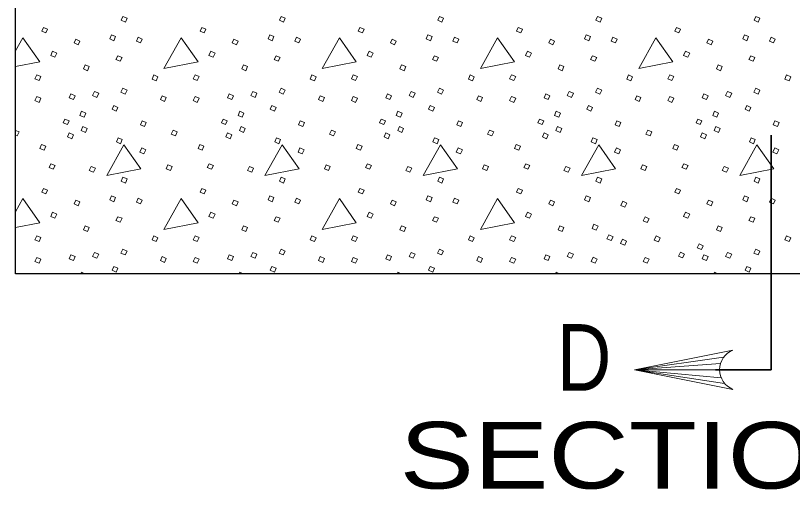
# Model space of a CAD drawing. Extents: x 1036.7 to 1070.7, y 883.9 to 905.9.
# Drawn here: x 1051.372 to 1054.169, y 893.033 to 894.74 of the extents above; entities that cross this region are included whole.
import ezdxf

# ---------------------------------------------------------------- set-up
doc = ezdxf.new("R2010")
doc.units = 0
doc.header["$LTSCALE"] = 0.062
doc.layers.add('1', color=7, linetype='Continuous', lineweight=13)

msp = doc.modelspace()

# ---------------------------------------------------------------- linework, layer by layer
at = {"layer": '1'}
for p, q in [((1051.39875, 894.66), (1051.37217, 894.61242)), ((1051.39875, 894.08033), (1051.37217, 894.03275)), ((1051.60742, 893.80992), (1051.60967, 893.8155)), ((1051.60967, 893.8155), (1051.62167, 893.80992)), ((1052.17717, 893.80992), (1052.17942, 893.8155)), ((1052.17942, 893.8155), (1052.19142, 893.80992)), ((1052.74692, 893.80992), (1052.74917, 893.8155)), ((1052.74917, 893.8155), (1052.76117, 893.80992)), ((1053.31658, 893.80992), (1053.31883, 893.8155)), ((1053.31883, 893.8155), (1053.33083, 893.80992)), ((1053.88633, 893.80992), (1053.88858, 893.8155)), ((1053.88858, 893.8155), (1053.90058, 893.80992)), ((1053.9215, 893.50883), (1053.601, 893.464)), ((1053.91058, 893.48667), (1053.601, 893.464)), ((1053.90733, 893.464), (1053.601, 893.464)), ((1053.913, 893.43525), (1053.601, 893.464)), ((1053.92525, 893.4145), (1053.601, 893.464))]:
    msp.add_line(p, q, dxfattribs=at)
at = {"layer": '1', "lineweight": 25}
for points in [[(1051.37217, 893.80992), (1051.37217, 899.32858), (1051.9695, 899.32858), (1051.9695, 900.49317)], [(1056.81275, 893.80992), (1053.87008, 893.80992), (1051.37217, 893.80992)]]:
    msp.add_lwpolyline(points, dxfattribs=at)
at = {"layer": '1'}
for points in [[(1051.75858, 894.73692), (1051.77358, 894.73092), (1051.76758, 894.716), (1051.75258, 894.723)], [(1052.32833, 894.73692), (1052.34333, 894.73092), (1052.33733, 894.716), (1052.32233, 894.723)], [(1052.89808, 894.73692), (1052.91308, 894.73092), (1052.90708, 894.716), (1052.89208, 894.723)], [(1053.46783, 894.73692), (1053.48283, 894.73092), (1053.47683, 894.716), (1053.46183, 894.723)], [(1054.0375, 894.73692), (1054.0525, 894.73092), (1054.0465, 894.716), (1054.0315, 894.723)], [(1051.47275, 894.697), (1051.48775, 894.691), (1051.48175, 894.677), (1051.46675, 894.683)], [(1052.0425, 894.697), (1052.0575, 894.691), (1052.0515, 894.677), (1052.0365, 894.683)], [(1052.61217, 894.697), (1052.62717, 894.691), (1052.62117, 894.677), (1052.60617, 894.683)], [(1053.18192, 894.697), (1053.19692, 894.691), (1053.19092, 894.677), (1053.17592, 894.683)], [(1053.75167, 894.697), (1053.76667, 894.691), (1053.76067, 894.677), (1053.74567, 894.683)], [(1051.58867, 894.655), (1051.60367, 894.648), (1051.59767, 894.634), (1051.58267, 894.641)], [(1051.71758, 894.67), (1051.73258, 894.664), (1051.72658, 894.649), (1051.71167, 894.656)], [(1051.81358, 894.662), (1051.82858, 894.655), (1051.82258, 894.641), (1051.80758, 894.647)], [(1051.9685, 894.66), (1051.9065, 894.54908), (1052.0295, 894.57308)], [(1052.15842, 894.655), (1052.17342, 894.648), (1052.16742, 894.634), (1052.15242, 894.641)], [(1052.28733, 894.67), (1052.30233, 894.664), (1052.29633, 894.649), (1052.28133, 894.656)], [(1052.38333, 894.662), (1052.39833, 894.655), (1052.39233, 894.641), (1052.37733, 894.647)], [(1052.53825, 894.66), (1052.47625, 894.54908), (1052.59917, 894.57308)], [(1052.72817, 894.655), (1052.74317, 894.648), (1052.73717, 894.634), (1052.72217, 894.641)], [(1052.85708, 894.67), (1052.87208, 894.664), (1052.86608, 894.649), (1052.85108, 894.656)], [(1052.95308, 894.662), (1052.968, 894.655), (1052.962, 894.641), (1052.94708, 894.647)], [(1053.108, 894.66), (1053.046, 894.54908), (1053.16892, 894.57308)], [(1053.29792, 894.655), (1053.31283, 894.648), (1053.30683, 894.634), (1053.29192, 894.641)], [(1053.42683, 894.67), (1053.44183, 894.664), (1053.43583, 894.649), (1053.42083, 894.656)], [(1053.52275, 894.662), (1053.53775, 894.655), (1053.53175, 894.641), (1053.51675, 894.647)], [(1053.67767, 894.66), (1053.61575, 894.54908), (1053.73867, 894.57308)], [(1053.86758, 894.655), (1053.88258, 894.648), (1053.87658, 894.634), (1053.86158, 894.641)], [(1053.99658, 894.67), (1054.01158, 894.664), (1054.00558, 894.649), (1053.99058, 894.656)], [(1054.0925, 894.662), (1054.1075, 894.655), (1054.1015, 894.641), (1054.0865, 894.647)], [(1051.50575, 894.611), (1051.52075, 894.604), (1051.51375, 894.59), (1051.49875, 894.596)], [(1051.74058, 894.595), (1051.75558, 894.589), (1051.74858, 894.57508), (1051.73358, 894.58108)], [(1052.07542, 894.611), (1052.09042, 894.604), (1052.08342, 894.59), (1052.0685, 894.596)], [(1052.31033, 894.595), (1052.32533, 894.589), (1052.31833, 894.57508), (1052.30333, 894.58108)], [(1052.64517, 894.611), (1052.66017, 894.604), (1052.65317, 894.59), (1052.63817, 894.596)], [(1052.88008, 894.595), (1052.89508, 894.589), (1052.88808, 894.57508), (1052.87308, 894.58108)], [(1053.21492, 894.611), (1053.22992, 894.604), (1053.22292, 894.59), (1053.20792, 894.596)], [(1053.44983, 894.595), (1053.46483, 894.589), (1053.45783, 894.57508), (1053.44283, 894.58108)], [(1053.78467, 894.611), (1053.79967, 894.604), (1053.79267, 894.59), (1053.77767, 894.596)], [(1054.0195, 894.595), (1054.0345, 894.589), (1054.0275, 894.57508), (1054.0125, 894.58108)], [(1051.62267, 894.56208), (1051.63767, 894.55608), (1051.63167, 894.54108), (1051.61667, 894.54808)], [(1052.19242, 894.56208), (1052.20742, 894.55608), (1052.20142, 894.54108), (1052.18642, 894.54808)], [(1052.76217, 894.56208), (1052.77708, 894.55608), (1052.77117, 894.54108), (1052.75617, 894.54808)], [(1053.33183, 894.56208), (1053.34683, 894.55608), (1053.34083, 894.54108), (1053.32583, 894.54808)], [(1053.90158, 894.56208), (1053.91658, 894.55608), (1053.91058, 894.54108), (1053.89558, 894.54808)], [(1051.44875, 894.52608), (1051.46375, 894.52008), (1051.45675, 894.50608), (1051.44175, 894.51208)], [(1051.86958, 894.52608), (1051.88458, 894.51908), (1051.87858, 894.50508), (1051.86358, 894.51108)], [(1052.0185, 894.52608), (1052.0335, 894.52008), (1052.0265, 894.50608), (1052.0115, 894.51208)], [(1052.43925, 894.52608), (1052.45425, 894.51908), (1052.44825, 894.50508), (1052.43325, 894.51108)], [(1052.58825, 894.52608), (1052.60317, 894.52008), (1052.59625, 894.50608), (1052.58125, 894.51208)], [(1053.009, 894.52608), (1053.024, 894.51908), (1053.018, 894.50508), (1053.003, 894.51108)], [(1053.15792, 894.52608), (1053.17292, 894.52008), (1053.16592, 894.50608), (1053.15092, 894.51208)], [(1053.57875, 894.52608), (1053.59375, 894.51908), (1053.58775, 894.50508), (1053.57275, 894.51108)], [(1053.72767, 894.52608), (1053.74267, 894.52008), (1053.73567, 894.50608), (1053.72067, 894.51208)], [(1054.1485, 894.52608), (1054.1635, 894.51908), (1054.1575, 894.50508), (1054.1425, 894.51108)], [(1051.75858, 894.47808), (1051.77358, 894.47108), (1051.76658, 894.45708), (1051.75158, 894.46408)], [(1052.32833, 894.47808), (1052.34333, 894.47108), (1052.33633, 894.45708), (1052.32133, 894.46408)], [(1052.89808, 894.47808), (1052.91308, 894.47108), (1052.90608, 894.45708), (1052.89108, 894.46408)], [(1053.46783, 894.47808), (1053.48283, 894.47108), (1053.47583, 894.45708), (1053.46083, 894.46408)], [(1054.0375, 894.47808), (1054.0525, 894.47108), (1054.0455, 894.45708), (1054.0305, 894.46408)], [(1051.44875, 894.44808), (1051.46375, 894.44217), (1051.45675, 894.42717), (1051.44175, 894.43417)], [(1051.57167, 894.45808), (1051.58667, 894.45108), (1051.58067, 894.43717), (1051.56567, 894.44308)], [(1051.65667, 894.46608), (1051.67167, 894.46008), (1051.66467, 894.44508), (1051.64967, 894.45208)], [(1051.8995, 894.45108), (1051.9145, 894.44408), (1051.9085, 894.43017), (1051.8935, 894.43717)], [(1052.0185, 894.44808), (1052.0335, 894.44217), (1052.0265, 894.42717), (1052.0115, 894.43417)], [(1052.14142, 894.45808), (1052.15642, 894.45108), (1052.15042, 894.43717), (1052.13542, 894.44308)], [(1052.22642, 894.46608), (1052.24142, 894.46008), (1052.23442, 894.44508), (1052.21942, 894.45208)], [(1052.46925, 894.45108), (1052.48425, 894.44408), (1052.47825, 894.43017), (1052.46325, 894.43717)], [(1052.58825, 894.44808), (1052.60317, 894.44217), (1052.59625, 894.42717), (1052.58125, 894.43417)], [(1052.71117, 894.45808), (1052.72617, 894.45108), (1052.72017, 894.43717), (1052.70517, 894.44308)], [(1052.79608, 894.46608), (1052.81108, 894.46008), (1052.80408, 894.44508), (1052.78908, 894.45208)], [(1053.039, 894.45108), (1053.054, 894.44408), (1053.048, 894.43017), (1053.033, 894.43717)], [(1053.15792, 894.44808), (1053.17292, 894.44217), (1053.16592, 894.42717), (1053.15092, 894.43417)], [(1053.28092, 894.45808), (1053.29592, 894.45108), (1053.28992, 894.43717), (1053.27492, 894.44308)], [(1053.36583, 894.46608), (1053.38083, 894.46008), (1053.37383, 894.44508), (1053.35883, 894.45208)], [(1053.60875, 894.45108), (1053.62375, 894.44408), (1053.61775, 894.43017), (1053.60275, 894.43717)], [(1053.72767, 894.44808), (1053.74267, 894.44217), (1053.73567, 894.42717), (1053.72067, 894.43417)], [(1053.85058, 894.45808), (1053.86558, 894.45108), (1053.85958, 894.43717), (1053.84458, 894.44308)], [(1053.93558, 894.46608), (1053.95058, 894.46008), (1053.94358, 894.44508), (1053.92858, 894.45208)], [(1051.60967, 894.39517), (1051.62467, 894.38817), (1051.61867, 894.37417), (1051.60367, 894.38017)], [(1051.72558, 894.41617), (1051.74058, 894.40917), (1051.73458, 894.39517), (1051.71958, 894.40217)], [(1052.17942, 894.39517), (1052.19442, 894.38817), (1052.18842, 894.37417), (1052.17342, 894.38017)], [(1052.29533, 894.41617), (1052.31033, 894.40917), (1052.30433, 894.39517), (1052.28933, 894.40217)], [(1052.74917, 894.39517), (1052.76417, 894.38817), (1052.75817, 894.37417), (1052.74317, 894.38017)], [(1052.86508, 894.41617), (1052.88008, 894.40917), (1052.87408, 894.39517), (1052.85908, 894.40217)], [(1053.31883, 894.39517), (1053.33383, 894.38817), (1053.32783, 894.37417), (1053.31283, 894.38017)], [(1053.43483, 894.41617), (1053.44983, 894.40917), (1053.44383, 894.39517), (1053.42883, 894.40217)], [(1053.88858, 894.39517), (1053.90358, 894.38817), (1053.89758, 894.37417), (1053.88258, 894.38017)], [(1054.00458, 894.41617), (1054.0195, 894.40917), (1054.01358, 894.39517), (1053.99858, 894.40217)], [(1051.54967, 894.36717), (1051.56467, 894.36117), (1051.55867, 894.34717), (1051.54367, 894.35317)], [(1052.11942, 894.36717), (1052.13442, 894.36117), (1052.12842, 894.34717), (1052.11342, 894.35317)], [(1052.68917, 894.36717), (1052.70417, 894.36117), (1052.69817, 894.34717), (1052.68317, 894.35317)], [(1053.25892, 894.36717), (1053.27392, 894.36117), (1053.26792, 894.34717), (1053.25292, 894.35317)], [(1053.82867, 894.36717), (1053.84358, 894.36117), (1053.83767, 894.34717), (1053.82267, 894.35317)], [(1051.61467, 894.34017), (1051.62967, 894.33317), (1051.62367, 894.31917), (1051.60867, 894.32617)], [(1051.82758, 894.36117), (1051.84258, 894.35417), (1051.83658, 894.34017), (1051.82158, 894.34617)], [(1052.18442, 894.34017), (1052.19942, 894.33317), (1052.19342, 894.31917), (1052.17842, 894.32617)], [(1052.39733, 894.36117), (1052.41233, 894.35417), (1052.40633, 894.34017), (1052.39133, 894.34617)], [(1052.75417, 894.34017), (1052.76917, 894.33317), (1052.76317, 894.31917), (1052.74817, 894.32617)], [(1052.967, 894.36117), (1052.982, 894.35417), (1052.976, 894.34017), (1052.961, 894.34617)], [(1053.32383, 894.34017), (1053.33883, 894.33317), (1053.33283, 894.31917), (1053.31783, 894.32617)], [(1053.53675, 894.36117), (1053.55175, 894.35417), (1053.54575, 894.34017), (1053.53075, 894.34617)], [(1053.89358, 894.34017), (1053.90858, 894.33317), (1053.90258, 894.31917), (1053.88758, 894.32617)], [(1054.1065, 894.36117), (1054.1215, 894.35417), (1054.1155, 894.34017), (1054.1005, 894.34617)], [(1051.56567, 894.31717), (1051.58067, 894.31017), (1051.57467, 894.29625), (1051.55967, 894.30317)], [(1051.9395, 894.32717), (1051.9545, 894.32117), (1051.9475, 894.30617), (1051.9325, 894.31317)], [(1052.13542, 894.31717), (1052.15042, 894.31017), (1052.14442, 894.29625), (1052.12942, 894.30317)], [(1052.50925, 894.32717), (1052.52425, 894.32117), (1052.51725, 894.30617), (1052.50225, 894.31317)], [(1052.70517, 894.31717), (1052.72017, 894.31017), (1052.71417, 894.29625), (1052.69917, 894.30317)], [(1053.079, 894.32717), (1053.094, 894.32117), (1053.087, 894.30617), (1053.072, 894.31317)], [(1053.27492, 894.31717), (1053.28992, 894.31017), (1053.28392, 894.29625), (1053.26892, 894.30317)], [(1053.64875, 894.32717), (1053.66367, 894.32117), (1053.65675, 894.30617), (1053.64175, 894.31317)], [(1053.84458, 894.31717), (1053.85958, 894.31017), (1053.85358, 894.29625), (1053.83867, 894.30317)], [(1051.74158, 894.29917), (1051.75658, 894.29325), (1051.75058, 894.27825), (1051.73558, 894.28525)], [(1052.31133, 894.29917), (1052.32633, 894.29325), (1052.32033, 894.27825), (1052.30533, 894.28525)], [(1052.88108, 894.29917), (1052.89608, 894.29325), (1052.89008, 894.27825), (1052.87508, 894.28525)], [(1053.45083, 894.29917), (1053.46583, 894.29325), (1053.45983, 894.27825), (1053.44483, 894.28525)], [(1054.0205, 894.29917), (1054.0355, 894.29325), (1054.0295, 894.27825), (1054.01458, 894.28525)], [(1051.46575, 894.27525), (1051.48075, 894.26925), (1051.47475, 894.25525), (1051.45975, 894.26125)], [(1051.76258, 894.27425), (1051.70067, 894.16325), (1051.82358, 894.18725)], [(1051.82658, 894.26325), (1051.84158, 894.25625), (1051.83458, 894.24225), (1051.81958, 894.24825)], [(1052.0355, 894.27525), (1052.0505, 894.26925), (1052.0445, 894.25525), (1052.0295, 894.26125)], [(1052.33233, 894.27425), (1052.27033, 894.16325), (1052.39333, 894.18725)], [(1052.39633, 894.26325), (1052.41133, 894.25625), (1052.40433, 894.24225), (1052.38933, 894.24825)], [(1052.60517, 894.27525), (1052.62017, 894.26925), (1052.61417, 894.25525), (1052.59917, 894.26125)], [(1052.90208, 894.27425), (1052.84008, 894.16325), (1052.963, 894.18725)], [(1052.966, 894.26325), (1052.981, 894.25625), (1052.974, 894.24225), (1052.959, 894.24825)], [(1053.17492, 894.27525), (1053.18992, 894.26925), (1053.18392, 894.25525), (1053.16892, 894.26125)], [(1053.47183, 894.27425), (1053.40983, 894.16325), (1053.53275, 894.18725)], [(1053.53575, 894.26325), (1053.55075, 894.25625), (1053.54375, 894.24225), (1053.52875, 894.24825)], [(1053.74467, 894.27525), (1053.75967, 894.26925), (1053.75367, 894.25525), (1053.73867, 894.26125)], [(1054.0415, 894.27425), (1053.97958, 894.16325), (1054.1025, 894.18725)], [(1054.1055, 894.26325), (1054.1205, 894.25625), (1054.1135, 894.24225), (1054.0985, 894.24825)], [(1051.49975, 894.20625), (1051.51475, 894.20025), (1051.50775, 894.18625), (1051.49275, 894.19225)], [(1051.64467, 894.19625), (1051.65967, 894.19025), (1051.65267, 894.17625), (1051.63767, 894.18225)], [(1051.9205, 894.20225), (1051.9355, 894.19625), (1051.9295, 894.18225), (1051.9145, 894.18825)], [(1052.0695, 894.20625), (1052.08442, 894.20025), (1052.07742, 894.18625), (1052.0625, 894.19225)], [(1052.21442, 894.19625), (1052.22942, 894.19025), (1052.22242, 894.17625), (1052.20742, 894.18225)], [(1052.49025, 894.20225), (1052.50525, 894.19625), (1052.49925, 894.18225), (1052.48425, 894.18825)], [(1052.63917, 894.20625), (1052.65417, 894.20025), (1052.64717, 894.18625), (1052.63217, 894.19225)], [(1052.78408, 894.19625), (1052.79908, 894.19025), (1052.79208, 894.17625), (1052.77708, 894.18225)], [(1053.06, 894.20225), (1053.075, 894.19625), (1053.069, 894.18225), (1053.054, 894.18825)], [(1053.20892, 894.20625), (1053.22392, 894.20025), (1053.21692, 894.18625), (1053.20192, 894.19225)], [(1053.35383, 894.19625), (1053.36883, 894.19025), (1053.36183, 894.17625), (1053.34683, 894.18225)], [(1053.62975, 894.20225), (1053.64475, 894.19625), (1053.63875, 894.18225), (1053.62375, 894.18825)], [(1053.77867, 894.20625), (1053.79367, 894.20025), (1053.78667, 894.18625), (1053.77167, 894.19225)], [(1053.92358, 894.19625), (1053.93858, 894.19025), (1053.93158, 894.17625), (1053.91658, 894.18225)], [(1051.75858, 894.15725), (1051.77358, 894.15125), (1051.76758, 894.13633), (1051.75258, 894.14333)], [(1052.32833, 894.15725), (1052.34333, 894.15125), (1052.33733, 894.13633), (1052.32233, 894.14333)], [(1052.89808, 894.15725), (1052.91308, 894.15125), (1052.90708, 894.13633), (1052.89208, 894.14333)], [(1053.46783, 894.15725), (1053.48283, 894.15125), (1053.47683, 894.13633), (1053.46183, 894.14333)], [(1054.0375, 894.15725), (1054.0525, 894.15125), (1054.0465, 894.13633), (1054.0315, 894.14333)], [(1051.47275, 894.11733), (1051.48775, 894.11133), (1051.48175, 894.09733), (1051.46675, 894.10333)], [(1052.0425, 894.11733), (1052.0575, 894.11133), (1052.0515, 894.09733), (1052.0365, 894.10333)], [(1052.61217, 894.11733), (1052.62717, 894.11133), (1052.62117, 894.09733), (1052.60617, 894.10333)], [(1053.18192, 894.11733), (1053.19692, 894.11133), (1053.19092, 894.09733), (1053.17592, 894.10333)], [(1053.75167, 894.11733), (1053.76667, 894.11133), (1053.76067, 894.09733), (1053.74567, 894.10333)], [(1051.71758, 894.09033), (1051.73258, 894.08433), (1051.72658, 894.06933), (1051.71167, 894.07633)], [(1052.28733, 894.09033), (1052.30233, 894.08433), (1052.29633, 894.06933), (1052.28133, 894.07633)], [(1052.85708, 894.09033), (1052.87208, 894.08433), (1052.86608, 894.06933), (1052.85108, 894.07633)], [(1053.42683, 894.09033), (1053.44183, 894.08433), (1053.43583, 894.06933), (1053.42083, 894.07633)], [(1053.99658, 894.09033), (1054.01158, 894.08433), (1054.00558, 894.06933), (1053.99058, 894.07633)], [(1051.58867, 894.07533), (1051.60367, 894.06833), (1051.59767, 894.05433), (1051.58267, 894.06133)], [(1051.81358, 894.08233), (1051.82858, 894.07533), (1051.82258, 894.06133), (1051.80758, 894.06733)], [(1051.9685, 894.08033), (1051.9065, 893.96942), (1052.0295, 893.99342)], [(1052.15842, 894.07533), (1052.17342, 894.06833), (1052.16742, 894.05433), (1052.15242, 894.06133)], [(1052.38333, 894.08233), (1052.39833, 894.07533), (1052.39233, 894.06133), (1052.37733, 894.06733)], [(1052.53825, 894.08033), (1052.47625, 893.96942), (1052.59917, 893.99342)], [(1052.72817, 894.07533), (1052.74317, 894.06833), (1052.73717, 894.05433), (1052.72217, 894.06133)], [(1052.95308, 894.08233), (1052.968, 894.07533), (1052.962, 894.06133), (1052.94708, 894.06733)], [(1053.108, 894.08033), (1053.046, 893.96942), (1053.16892, 893.99342)], [(1053.29792, 894.07533), (1053.31283, 894.06833), (1053.30683, 894.05433), (1053.29192, 894.06133)], [(1053.55825, 894.07108), (1053.57325, 894.06408), (1053.56625, 894.05008), (1053.55125, 894.05608)], [(1053.86758, 894.07533), (1053.88258, 894.06833), (1053.87658, 894.05433), (1053.86158, 894.06133)], [(1054.0925, 894.08233), (1054.1075, 894.07533), (1054.1015, 894.06133), (1054.0865, 894.06733)], [(1051.50575, 894.03133), (1051.52075, 894.02433), (1051.51375, 894.01033), (1051.49875, 894.01633)], [(1052.07542, 894.03133), (1052.09042, 894.02433), (1052.08342, 894.01033), (1052.0685, 894.01633)], [(1052.64517, 894.03133), (1052.66017, 894.02433), (1052.65317, 894.01033), (1052.63817, 894.01633)], [(1053.21492, 894.03133), (1053.22992, 894.02433), (1053.22292, 894.01033), (1053.20792, 894.01633)], [(1053.78467, 894.03133), (1053.79967, 894.02433), (1053.79267, 894.01033), (1053.77767, 894.01633)], [(1051.74058, 894.01533), (1051.75558, 894.00942), (1051.74858, 893.99542), (1051.73358, 894.00142)], [(1052.31033, 894.01533), (1052.32533, 894.00942), (1052.31833, 893.99542), (1052.30333, 894.00142)], [(1052.88008, 894.01533), (1052.89508, 894.00942), (1052.88808, 893.99542), (1052.87308, 894.00142)], [(1053.63858, 894.01508), (1053.65358, 894.00808), (1053.64658, 893.99408), (1053.63158, 894.00008)], [(1054.0195, 894.01533), (1054.0345, 894.00942), (1054.0275, 893.99542), (1054.0125, 894.00142)], [(1051.62267, 893.98242), (1051.63767, 893.97642), (1051.63167, 893.96142), (1051.61667, 893.96842)], [(1052.19242, 893.98242), (1052.20742, 893.97642), (1052.20142, 893.96142), (1052.18642, 893.96842)], [(1052.76217, 893.98242), (1052.77708, 893.97642), (1052.77117, 893.96142), (1052.75617, 893.96842)], [(1053.33183, 893.98242), (1053.34683, 893.97642), (1053.34083, 893.96142), (1053.32583, 893.96842)], [(1053.45483, 893.98792), (1053.46983, 893.98092), (1053.46283, 893.96692), (1053.44783, 893.97292)], [(1053.90158, 893.98242), (1053.91658, 893.97642), (1053.91058, 893.96142), (1053.89558, 893.96842)], [(1051.44875, 893.94642), (1051.46375, 893.94042), (1051.45675, 893.92642), (1051.44175, 893.93242)], [(1051.86958, 893.94642), (1051.88458, 893.93942), (1051.87858, 893.92542), (1051.86358, 893.93142)], [(1052.0185, 893.94642), (1052.0335, 893.94042), (1052.0265, 893.92642), (1052.0115, 893.93242)], [(1052.43925, 893.94642), (1052.45425, 893.93942), (1052.44825, 893.92542), (1052.43325, 893.93142)], [(1052.58825, 893.94642), (1052.60317, 893.94042), (1052.59625, 893.92642), (1052.58125, 893.93242)], [(1053.009, 893.94642), (1053.024, 893.93942), (1053.018, 893.92542), (1053.003, 893.93142)], [(1053.15792, 893.94642), (1053.17292, 893.94042), (1053.16592, 893.92642), (1053.15092, 893.93242)], [(1053.50867, 893.95008), (1053.52367, 893.94308), (1053.51667, 893.92908), (1053.50167, 893.93508)], [(1053.6785, 893.946), (1053.6935, 893.939), (1053.6865, 893.925), (1053.6715, 893.931)], [(1054.1485, 893.94642), (1054.1635, 893.93942), (1054.1575, 893.92542), (1054.1425, 893.93142)], [(1053.55742, 893.93383), (1053.57242, 893.92683), (1053.56542, 893.91283), (1053.55042, 893.91883)], [(1053.83333, 893.91758), (1053.84833, 893.91058), (1053.84133, 893.89658), (1053.82633, 893.90258)], [(1051.75858, 893.89842), (1051.77358, 893.89142), (1051.76658, 893.87742), (1051.75158, 893.88442)], [(1052.32833, 893.89842), (1052.34333, 893.89142), (1052.33633, 893.87742), (1052.32133, 893.88442)], [(1052.89808, 893.89842), (1052.91308, 893.89142), (1052.90608, 893.87742), (1052.89108, 893.88442)], [(1054.0375, 893.89842), (1054.0525, 893.89142), (1054.0455, 893.87742), (1054.0305, 893.88442)], [(1051.44875, 893.86842), (1051.46375, 893.86242), (1051.45675, 893.8475), (1051.44175, 893.8545)], [(1051.57167, 893.87842), (1051.58667, 893.87142), (1051.58067, 893.8575), (1051.56567, 893.86342)], [(1051.65667, 893.88642), (1051.67167, 893.88042), (1051.66467, 893.86542), (1051.64967, 893.87242)], [(1051.8995, 893.87142), (1051.9145, 893.86442), (1051.9085, 893.8505), (1051.8935, 893.8575)], [(1052.0185, 893.86842), (1052.0335, 893.86242), (1052.0265, 893.8475), (1052.0115, 893.8545)], [(1052.14142, 893.87842), (1052.15642, 893.87142), (1052.15042, 893.8575), (1052.13542, 893.86342)], [(1052.22642, 893.88642), (1052.24142, 893.88042), (1052.23442, 893.86542), (1052.21942, 893.87242)], [(1052.46925, 893.87142), (1052.48425, 893.86442), (1052.47825, 893.8505), (1052.46325, 893.8575)], [(1052.58825, 893.86842), (1052.60317, 893.86242), (1052.59625, 893.8475), (1052.58125, 893.8545)], [(1052.71117, 893.87842), (1052.72617, 893.87142), (1052.72017, 893.8575), (1052.70517, 893.86342)], [(1052.79608, 893.88642), (1052.81108, 893.88042), (1052.80408, 893.86542), (1052.78908, 893.87242)], [(1053.039, 893.87142), (1053.054, 893.86442), (1053.048, 893.8505), (1053.033, 893.8575)], [(1053.15792, 893.86842), (1053.17292, 893.86242), (1053.16592, 893.8475), (1053.15092, 893.8545)], [(1053.28092, 893.87842), (1053.29592, 893.87142), (1053.28992, 893.8575), (1053.27492, 893.86342)], [(1053.36583, 893.88642), (1053.38083, 893.88042), (1053.37383, 893.86542), (1053.35883, 893.87242)], [(1053.45167, 893.86917), (1053.46667, 893.86217), (1053.45967, 893.84817), (1053.44467, 893.85417)], [(1053.63858, 893.86875), (1053.65358, 893.86183), (1053.64658, 893.84783), (1053.63158, 893.85383)], [(1053.76575, 893.88758), (1053.78075, 893.88058), (1053.77375, 893.86658), (1053.75875, 893.87258)], [(1053.85058, 893.87842), (1053.86558, 893.87142), (1053.85958, 893.8575), (1053.84458, 893.86342)], [(1053.93558, 893.88642), (1053.95058, 893.88042), (1053.94358, 893.86542), (1053.92858, 893.87242)], [(1051.72558, 893.8365), (1051.74058, 893.8295), (1051.73458, 893.8155), (1051.71958, 893.8225)], [(1052.29533, 893.8365), (1052.31033, 893.8295), (1052.30433, 893.8155), (1052.28933, 893.8225)], [(1052.86508, 893.8365), (1052.88008, 893.8295), (1052.87408, 893.8155), (1052.85908, 893.8225)], [(1054.00458, 893.8365), (1054.0195, 893.8295), (1054.01358, 893.8155), (1053.99858, 893.8225)]]:
    msp.add_lwpolyline(points, close=True, dxfattribs=at)
for points in [[(1051.37217, 894.556), (1051.45975, 894.57308), (1051.39875, 894.66)], [(1051.37217, 894.32617), (1051.38475, 894.32117), (1051.37775, 894.30617), (1051.37217, 894.30875)], [(1051.37217, 893.97633), (1051.45975, 893.99342), (1051.39875, 894.08033)], [(1053.955, 893.39325), (1053.601, 893.464), (1053.955, 893.53483)]]:
    msp.add_lwpolyline(points, dxfattribs=at)
at = {"layer": '1', "lineweight": 35}
msp.add_lwpolyline([(1054.09242, 894.30958), (1054.09242, 893.464), (1053.8925, 893.464)], dxfattribs=at)
at = {"layer": '1'}
msp.add_arc((1053.98358, 893.4641), 0.0764, 112.08782, 247.91395, dxfattribs=at)

# ---------------------------------------------------------------- texts
for s, width, p in [('D', 0.85, (1053.32058, 893.38842)), ('SECTION C-C', 1.25, (1052.75517, 893.03617))]:
    msp.add_text(s, height=0.24, dxfattribs=dict(at, width=width)).set_placement(p)

doc.saveas('drawing.dxf')
